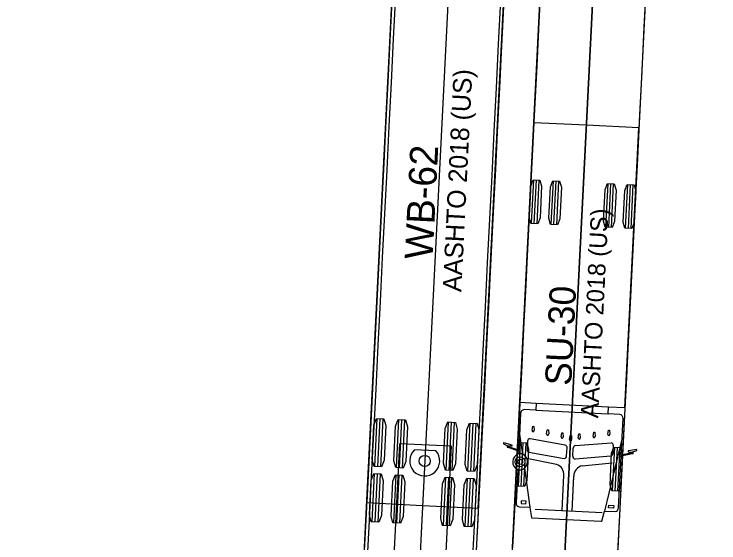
# Model space of a CAD drawing. Extents: x 260275 to 261282, y 610916 to 614143.
# Drawn here: x 260986.2 to 261039.9, y 611751.1 to 611791.3 of the extents above; entities that cross this region are included whole.
import ezdxf

# ---------------------------------------------------------------- set-up
doc = ezdxf.new("R2010")
doc.units = 0
doc.layers.add('GE_X_Alignment', color=7, linetype='Continuous')
doc.layers.add('UT_X_Water_Cells', color=7, linetype='Continuous')

msp = doc.modelspace()

# ---------------------------------------------------------------- linework, layer by layer
at = {"layer": 'GE_X_Alignment'}
msp.add_line((260986.249, 610915.954), (261148.276, 614142.838), dxfattribs=at)
at = {"layer": 'UT_X_Water_Cells'}
for p, q in [((261044.031, 612066.726), (261023.69, 611661.632)), ((261031.95, 612045.486), (261010.925, 611626.741)), ((261025.603, 611775.331), (261025.77, 611778.66)), ((261025.811, 611775.321), (261025.978, 611778.65)), ((261026.019, 611775.31), (261026.186, 611778.64)), ((261027.101, 611775.256), (261027.268, 611778.585)), ((261027.309, 611775.246), (261027.476, 611778.575)), ((261027.517, 611775.235), (261027.684, 611778.564)), ((261031.263, 611775.047), (261031.43, 611778.376)), ((261031.471, 611775.037), (261031.638, 611778.366)), ((261031.679, 611775.026), (261031.846, 611778.355)), ((261032.761, 611774.972), (261032.928, 611778.301)), ((261032.969, 611774.962), (261033.136, 611778.291)), ((261033.177, 611774.951), (261033.344, 611778.28)), ((261025.964, 611761.676), (261031.449, 611761.401)), ((261025.938, 611761.145), (261031.423, 611760.87)), ((261013.682, 611756.851), (261013.866, 611760.513)), ((261013.911, 611756.839), (261014.095, 611760.501)), ((261014.14, 611756.828), (261014.324, 611760.49)), ((261015.33, 611756.768), (261015.514, 611760.43)), ((261015.559, 611756.756), (261015.743, 611760.419)), ((261015.788, 611756.745), (261015.972, 611760.407)), ((261019.109, 611756.578), (261019.292, 611760.24)), ((261019.337, 611756.567), (261019.521, 611760.229)), ((261019.566, 611756.555), (261019.75, 611760.217)), ((261020.756, 611756.495), (261020.94, 611760.158)), ((261020.985, 611756.484), (261021.169, 611760.146)), ((261021.214, 611756.472), (261021.398, 611760.135)), ((261025.647, 611759.618), (261025.698, 611759.916)), ((261025.698, 611759.916), (261025.78, 611759.912)), ((261025.78, 611759.912), (261025.801, 611759.61)), ((261026.752, 611759.352), (261026.803, 611759.65)), ((261026.803, 611759.65), (261026.885, 611759.645)), ((261026.885, 611759.645), (261026.906, 611759.344)), ((261027.859, 611759.114), (261027.91, 611759.411)), ((261027.91, 611759.411), (261027.992, 611759.407)), ((261027.992, 611759.407), (261028.013, 611759.106)), ((261030.279, 611759.161), (261030.33, 611759.473)), ((261030.33, 611759.473), (261030.412, 611759.468)), ((261030.412, 611759.468), (261030.433, 611759.153)), ((261031.405, 611759.329), (261031.456, 611759.627)), ((261031.456, 611759.627), (261031.538, 611759.622)), ((261031.538, 611759.622), (261031.559, 611759.321)), ((261024.691, 611759.33), (261024.907, 611757.796)), ((261028.164, 611758.486), (261025.49, 611758.972)), ((261028.498, 611758.913), (261028.549, 611759.211)), ((261028.549, 611759.211), (261028.631, 611759.207)), ((261028.631, 611759.207), (261028.652, 611758.906)), ((261029.154, 611759.049), (261029.205, 611759.346)), ((261029.205, 611759.346), (261029.287, 611759.342)), ((261029.287, 611759.342), (261029.308, 611759.041)), ((261032.481, 611758.939), (261031.141, 611753.471)), ((261024.6, 611755.357), (261024.767, 611758.686)), ((261024.808, 611755.346), (261024.975, 611758.675)), ((261025.016, 611755.336), (261025.183, 611758.665)), ((261025.299, 611758.78), (261025.268, 611758.164)), ((261028.942, 611758.447), (261031.65, 611758.663)), ((261031.821, 611758.452), (261031.791, 611757.836)), ((261018.327, 611758.049), (261016.713, 611758.13)), ((261025.409, 611757.954), (261028.083, 611757.468)), ((261028.274, 611757.661), (261028.305, 611758.277)), ((261028.749, 611757.637), (261028.78, 611758.253)), ((261031.758, 611754.997), (261031.925, 611758.326)), ((261031.966, 611754.987), (261032.133, 611758.316)), ((261032.174, 611754.976), (261032.341, 611758.305)), ((261027.497, 611757.01), (261025.241, 611757.471)), ((261031.629, 611757.642), (261028.92, 611757.426)), ((261029.457, 611756.912), (261031.736, 611757.143)), ((261013.471, 611752.656), (261013.655, 611756.318)), ((261013.7, 611752.644), (261013.884, 611756.307)), ((261013.929, 611752.633), (261014.113, 611756.295)), ((261015.119, 611752.573), (261015.303, 611756.235)), ((261015.348, 611752.562), (261015.532, 611756.224)), ((261015.577, 611752.55), (261015.761, 611756.212)), ((261024.556, 611756.631), (261024.429, 611754.111)), ((261025.059, 611756.721), (261025.477, 611753.755)), ((261018.898, 611752.383), (261019.082, 611756.046)), ((261019.127, 611752.372), (261019.311, 611756.034)), ((261019.356, 611752.361), (261019.54, 611756.023)), ((261020.546, 611752.301), (261020.73, 611755.963)), ((261020.775, 611752.289), (261020.959, 611755.951)), ((261021.004, 611752.278), (261021.187, 611755.94)), ((261027.92, 611753.51), (261028.054, 611756.174)), ((261028.685, 611753.471), (261028.819, 611756.136)), ((261024.812, 611754.245), (261024.802, 611754.051)), ((261024.802, 611754.051), (261025.18, 611754.032)), ((261025.19, 611754.226), (261024.812, 611754.245)), ((261025.18, 611754.032), (261025.19, 611754.226)), ((261025.886, 611753.612), (261030.985, 611753.356)), ((261031.464, 611753.717), (261031.474, 611753.911)), ((261031.842, 611753.698), (261031.464, 611753.717)), ((261031.474, 611753.911), (261031.852, 611753.892)), ((261031.852, 611753.892), (261031.842, 611753.698))]:
    msp.add_line(p, q, dxfattribs=at)
for points in [[(261009.34, 611680.102), (261030.965, 612110.617)], [(261039.447, 612110.045), (261018.12, 611685.301)], [(261020.965, 611687.133), (261041.34, 612092.893)], [(261049.322, 612092.345), (261028.546, 611678.469)], [(261015.491, 611801.98), (261015.468, 611801.981), (261013.065, 611754.112), (261017.309, 611753.898), (261021.554, 611753.685), (261023.958, 611801.554), (261023.935, 611801.555)], [(261026.331, 611793.982), (261026.164, 611790.654), (261025.997, 611787.325), (261025.83, 611783.996), (261025.662, 611780.668), (261025.495, 611777.339), (261025.328, 611774.011), (261025.161, 611770.682), (261024.994, 611767.353), (261024.827, 611764.025), (261024.66, 611760.696), (261024.492, 611757.368), (261024.325, 611754.039), (261024.158, 611750.71)], [(261026.331, 611793.979), (261026.164, 611790.651), (261025.996, 611787.322), (261025.829, 611783.993), (261025.662, 611780.665), (261025.495, 611777.336), (261025.328, 611774.008), (261025.161, 611770.679), (261024.994, 611767.35), (261024.827, 611764.022), (261024.659, 611760.693), (261024.492, 611757.364), (261024.325, 611754.036), (261024.158, 611750.707)], [(261015.029, 611793.23), (261014.862, 611789.901), (261014.695, 611786.572), (261014.528, 611783.244), (261014.36, 611779.915), (261014.193, 611776.586), (261014.026, 611773.258), (261013.859, 611769.929), (261013.692, 611766.6), (261013.525, 611763.272), (261013.358, 611759.943), (261013.19, 611756.614), (261013.023, 611753.286), (261012.856, 611749.957)], [(261034.321, 611793.581), (261034.154, 611790.253), (261033.987, 611786.924), (261033.819, 611783.595), (261033.652, 611780.267), (261033.485, 611776.938), (261033.318, 611773.609), (261033.151, 611770.281), (261032.984, 611766.952), (261032.817, 611763.624), (261032.649, 611760.295), (261032.482, 611756.966), (261032.315, 611753.638), (261032.148, 611750.309)], [(261034.321, 611793.578), (261034.154, 611790.249), (261033.986, 611786.921), (261033.819, 611783.592), (261033.652, 611780.264), (261033.485, 611776.935), (261033.318, 611773.606), (261033.151, 611770.278), (261032.984, 611766.949), (261032.816, 611763.62), (261032.649, 611760.292), (261032.482, 611756.963), (261032.315, 611753.635), (261032.148, 611750.306)], [(261015.253, 611792.709), (261015.086, 611789.38), (261014.919, 611786.052), (261014.752, 611782.723), (261014.585, 611779.394), (261014.417, 611776.066), (261014.25, 611772.737), (261014.083, 611769.408), (261013.916, 611766.08), (261013.749, 611762.751), (261013.582, 611759.422), (261013.415, 611756.094), (261013.247, 611752.765), (261013.08, 611749.436)], [(261023.518, 611792.803), (261023.351, 611789.475), (261023.184, 611786.146), (261023.017, 611782.817), (261022.85, 611779.489), (261022.683, 611776.16), (261022.515, 611772.831), (261022.348, 611769.503), (261022.181, 611766.174), (261022.014, 611762.845), (261021.847, 611759.517), (261021.68, 611756.188), (261021.513, 611752.859), (261021.345, 611749.531)], [(261023.243, 611792.308), (261023.076, 611788.979), (261022.909, 611785.65), (261022.742, 611782.322), (261022.574, 611778.993), (261022.407, 611775.664), (261022.24, 611772.336), (261022.073, 611769.007), (261021.906, 611765.678), (261021.739, 611762.35), (261021.572, 611759.021), (261021.405, 611755.693), (261021.237, 611752.364), (261021.07, 611749.035)], [(261032.321, 611760.825), (261031.426, 611760.87), (261031.423, 611760.874), (261031.449, 611761.4), (261031.46, 611761.4), (261032.702, 611761.338), (261033.769, 611782.598), (261029.774, 611782.798), (261025.779, 611782.999), (261024.712, 611761.739), (261025.953, 611761.677), (261025.964, 611761.675), (261025.938, 611761.149), (261025.935, 611761.145), (261025.04, 611761.19)], [(261024.769, 611760.888), (261024.63, 611758.117), (261024.625, 611758.106), (261023.82, 611758.366), (261023.819, 611758.366)], [(261033.252, 611757.892), (261033.252, 611757.892), (261032.425, 611757.714), (261032.42, 611757.726), (261032.56, 611760.497)], [(261019.622, 611747.775), (261018.993, 611747.806), (261019.524, 611758.393), (261015.556, 611758.592), (261015.024, 611748.006), (261014.395, 611748.037)], [(261023.809, 611758.387), (261023.811, 611758.431), (261023.811, 611758.431), (261024.129, 611758.424), (261024.131, 611758.424), (261024.134, 611758.48), (261024.131, 611758.481), (261023.483, 611758.653), (261023.48, 611758.653), (261023.477, 611758.588), (261023.765, 611758.442), (261023.765, 611758.442), (261023.763, 611758.394)], [(261023.8, 611758.32), (261023.801, 611758.32), (261024.62, 611758.052), (261024.626, 611758.04), (261024.615, 611757.812)], [(261032.219, 611753.72), (261032.416, 611757.648), (261032.424, 611757.66), (261033.266, 611757.844), (261033.267, 611757.844)], [(261033.311, 611757.915), (261033.314, 611757.962), (261033.314, 611757.963), (261033.615, 611758.079), (261033.618, 611758.144), (261033.616, 611758.144), (261032.953, 611758.038), (261032.95, 611758.037), (261032.948, 611757.981), (261032.95, 611757.981), (261033.267, 611757.957), (261033.267, 611757.956), (261033.264, 611757.912)], [(261024.667, 611753.796), (261025.474, 611753.755), (261025.478, 611753.751), (261025.588, 611752.973), (261025.63, 611752.969), (261028.27, 611752.836), (261030.91, 611752.703), (261030.952, 611752.703), (261031.14, 611753.466), (261031.144, 611753.471), (261031.951, 611753.43)]]:
    msp.add_lwpolyline(points, dxfattribs=at)
for points in [[(261026.071, 611775.308), (261025.551, 611775.334), (261025.418, 611775.808), (261025.539, 611778.205), (261025.719, 611778.663), (261026.238, 611778.637), (261026.371, 611778.163), (261026.251, 611775.766)], [(261027.569, 611775.233), (261027.05, 611775.259), (261026.916, 611775.733), (261027.037, 611778.13), (261027.217, 611778.588), (261027.736, 611778.562), (261027.869, 611778.088), (261027.749, 611775.691)], [(261031.73, 611775.024), (261031.211, 611775.05), (261031.078, 611775.524), (261031.198, 611777.921), (261031.378, 611778.379), (261031.897, 611778.353), (261032.031, 611777.879), (261031.91, 611775.482)], [(261033.228, 611774.948), (261032.709, 611774.975), (261032.576, 611775.448), (261032.696, 611777.845), (261032.876, 611778.304), (261033.396, 611778.278), (261033.529, 611777.804), (261033.408, 611775.407)], [(261014.197, 611756.825), (261013.625, 611756.854), (261013.479, 611757.375), (261013.611, 611760.012), (261013.809, 611760.516), (261014.38, 611760.487), (261014.527, 611759.966), (261014.394, 611757.329)], [(261015.845, 611756.742), (261015.273, 611756.771), (261015.127, 611757.292), (261015.259, 611759.929), (261015.457, 611760.433), (261016.028, 611760.404), (261016.175, 611759.883), (261016.042, 611757.246)], [(261019.623, 611756.552), (261019.052, 611756.581), (261018.905, 611757.102), (261019.038, 611759.739), (261019.236, 611760.243), (261019.807, 611760.214), (261019.953, 611759.693), (261019.821, 611757.056)], [(261021.271, 611756.47), (261020.7, 611756.498), (261020.553, 611757.02), (261020.686, 611759.656), (261020.884, 611760.16), (261021.455, 611760.132), (261021.601, 611759.61), (261021.469, 611756.974)], [(261025.068, 611755.333), (261024.548, 611755.359), (261024.415, 611755.833), (261024.536, 611758.23), (261024.716, 611758.688), (261025.235, 611758.662), (261025.368, 611758.188), (261025.248, 611755.791)], [(261032.225, 611754.974), (261031.706, 611755), (261031.573, 611755.474), (261031.693, 611757.871), (261031.873, 611758.329), (261032.393, 611758.303), (261032.526, 611757.829), (261032.405, 611755.432)], [(261013.986, 611752.63), (261013.415, 611752.659), (261013.268, 611753.18), (261013.401, 611755.817), (261013.599, 611756.321), (261014.17, 611756.292), (261014.316, 611755.771), (261014.184, 611753.134)], [(261015.634, 611752.547), (261015.063, 611752.576), (261014.916, 611753.097), (261015.049, 611755.734), (261015.246, 611756.238), (261015.818, 611756.209), (261015.964, 611755.688), (261015.832, 611753.051)], [(261019.412, 611752.358), (261018.841, 611752.386), (261018.695, 611752.908), (261018.827, 611755.544), (261019.025, 611756.048), (261019.596, 611756.02), (261019.743, 611755.498), (261019.61, 611752.862)], [(261021.06, 611752.275), (261020.489, 611752.304), (261020.343, 611752.825), (261020.475, 611755.462), (261020.673, 611755.966), (261021.244, 611755.937), (261021.391, 611755.416), (261021.258, 611752.779)]]:
    msp.add_lwpolyline(points, close=True, dxfattribs=at)
for centre, radius in [((261017.479, 611757.282), 0.424), ((261024.73, 611757.214), 0.374), ((261024.73, 611757.214), 0.193)]:
    msp.add_circle(centre, radius, dxfattribs=at)
for centre, radius, start, end in [((261025.092, 611760.872), 0.323, 99.2771, 177.1255), ((261032.237, 611760.513), 0.323, 357.1255, 74.9739), ((261025.735, 611759.595), 0.091, 165.4421, 259.6059), ((261025.711, 611759.596), 0.0909, 274.6094, 8.8446), ((261025.483, 611758.788), 0.184, 87.7181, 182.5893), ((261026.84, 611759.329), 0.091, 165.4421, 259.6059), ((261026.816, 611759.33), 0.0909, 274.6094, 8.8446), ((261027.947, 611759.091), 0.091, 165.4421, 259.6059), ((261027.923, 611759.092), 0.0909, 274.6094, 8.8446), ((261028.586, 611758.89), 0.091, 165.4421, 259.6059), ((261028.562, 611758.892), 0.091, 274.6451, 8.8089), ((261029.242, 611759.026), 0.0909, 165.4064, 259.6416), ((261029.218, 611759.027), 0.091, 274.6451, 8.8089), ((261030.367, 611759.152), 0.0909, 165.4064, 259.6416), ((261030.343, 611759.153), 0.091, 274.6451, 8.8089), ((261031.493, 611759.306), 0.0909, 165.4064, 259.6416), ((261031.469, 611759.307), 0.091, 274.6451, 8.8089), ((261023.783, 611758.357), 0.0418, 117.6187, 294.6336), ((261023.777, 611758.358), 0.0434, 11.039, 41.7118), ((261028.114, 611758.3), 0.193, 353.0637, 74.988), ((261028.973, 611758.257), 0.193, 99.263, 181.1873), ((261031.639, 611758.479), 0.184, 351.6617, 86.5329), ((261017.479, 611757.282), 1.143, 132.1255, 42.1255), ((261024.797, 611757.21), 0.628, 106.8788, 247.3705), ((261024.734, 611757.301), 0.524, 49.3845, 103.1846), ((261025.459, 611758.14), 0.193, 173.0686, 254.9831), ((261031.598, 611757.832), 0.193, 279.2679, 1.1824), ((261033.294, 611757.88), 0.0434, 132.5392, 163.212), ((261033.288, 611757.88), 0.0418, 239.6174, 56.6324), ((261024.662, 611757.224), 0.63, 356.4803, 48.8831), ((261028.09, 611757.652), 0.184, 267.7236, 2.5838), ((261028.932, 611757.61), 0.184, 171.6672, 266.5274), ((261024.661, 611757.209), 0.629, 309.1711, 357.8604), ((261027.287, 611756.267), 0.773, 353.1509, 74.235), ((261029.592, 611756.151), 0.773, 100.016, 181.1001), ((261024.726, 611757.128), 0.526, 251.0707, 309.3167), ((261024.708, 611754.075), 0.282, 172.4977, 261.5771), ((261031.938, 611753.712), 0.282, 272.6739, 1.7533)]:
    msp.add_arc(centre, radius, start, end, dxfattribs=at)

# ---------------------------------------------------------------- texts
for s, height, p in [('AASHTO 2018 (US)', 1.41667, (261020.258, 611770.106)), ('WB-62', 2.125, (261018.077, 611772.571)), ('AASHTO 2018 (US)', 1.33333, (261030.665, 611760.511)), ('SU-30', 2, (261028.619, 611762.974))]:
    msp.add_text(s, height=height, rotation=87.1255, dxfattribs=at).set_placement(p)

doc.saveas('drawing.dxf')
